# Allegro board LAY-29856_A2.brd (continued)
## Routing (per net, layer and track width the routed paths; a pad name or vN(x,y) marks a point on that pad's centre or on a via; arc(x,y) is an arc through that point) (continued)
SDA_USB_CONN_DP: length 4.6
  TOP w0.119: R190.1 123.38,82.36 123.38,82.62 U19.1 123.39,84.01 123.39,84.85 123.19,85.05 J23.3
SDA_USB_DN: length 5.5
  TOP w0.119: v1(124.84,80.06) 124.54,79.76 123.73,79.76 123.33,79.36 123.33,79.13 123.19,78.98 U16.4 ; R189.2 123.63,80.7 123.63,80.46 v1(123.83,80.26)
  BOTTOM w0.119: v1(124.84,80.06) 124.6,79.82 123.76,79.82 123.64,79.94 123.64,80.08 v1(123.83,80.26)
SDA_USB_DP: length 5.4
  TOP w0.119: U16.3 123.69,78.98 123.58,79.09 123.58,79.26 123.83,79.51 124.67,79.51 v1(124.84,79.34) ; R190.2 123.32,80.77 123.32,80.47 v1(123.11,80.26)
  BOTTOM w0.119: v1(124.84,79.34) 124.6,79.58 123.66,79.58 123.39,79.84 123.39,79.98 v1(123.11,80.26)
SDA_USB_P5V_SENSE: length 5.2
  TOP w0.127: U16.30 126.1,76.82 127.51,78.24 R200.2 R203.1
SDA_VOUT33: length 3.8
  TOP w0.127: U16.5 122.69,79.75 122.17,80.26 C162.1 122.17,81.03 R181.2
SDA_XTAL: length 6.6
  TOP w0.127: U16.18 121.69,73.04 119.89,71.25 119.63,71.25 C160.1 118.43,70.05 Y3.1
SDRAM_3V3: length 51.9
  TOP w0.381: v1(85.85,51.05) 86.49,51.69 88.27,51.69 v1(88.9,51.05) 89.53,51.69 91.82,51.69 v1(92.46,51.05) 93.09,51.69 94.82,51.69 95.45,51.05 ; U14.3 v1(102.65,58.33) ; U14.49 v1(100.25,51.44) ; v1(91.19,57.28) 90.68,57.28 89.79,58.17 82.55,58.17 82.3,58.42 C149.1 81.53,59.44 82.04,59.94 83.06,59.94 83.45,60.34 U14.27 ; 95.45,51.05 95.83,51.44 v1(98.81,51.44) ; 95.45,51.05 U14.43 ; U14.14 v1(93.85,58.67) ; U14.9 v1(97.85,58.67) ; U14.1 v1(104.25,58.29)
  BOTTOM w0.381: v1(88.9,51.05) R314.1 R315.1 ; R270.1 R269.1 v1(92.46,51.05) ; R268.1 98.81,52.45 ; R266.1 98.81,54.99 ; R265.1 98.81,56.26 ; R271.1 v1(85.85,51.05) ; C147.1 v1(98.81,51.44) ; R267.1 98.81,53.72
SEMC_A0: length 3.5
  TOP w0.127: R299.1 70.1,57.52 70.1,56.77 69.73,56.39 U1.142
SEMC_A1: length 3.3
  TOP w0.127: R300.1 70.61,57.14 70.61,56.39 70.12,55.89 U1.141
SEMC_A2: length 6.4
  TOP w0.127: U1.140 70.5,55.39 71.18,56.07 71.18,56.25 70.98,56.45 70.98,56.63 71.16,56.81 71.34,56.81 71.54,56.61 72.1,56.61 72.9,57.4 72.9,57.52 R301.1
SEMC_A3: length 5.3
  TOP w0.127: R302.1 72.52,56.13 71.75,56.13 70.51,54.89 U1.139
SEMC_A4: length 5.1
  TOP w0.127: U1.138 69.72,54.39 69.81,54.48 70.61,54.48 71.88,55.75 R303.1
SEMC_A5: length 4.9
  TOP w0.127: U1.137 69.72,53.89 69.97,54.14 70.7,54.14 71.3,54.74 R288.1
SEMC_A6: length 4.8
  TOP w0.127: U1.136 69.65,53.39 70.1,53.84 71.89,53.84 72.01,53.72 R289.1
SEMC_A7: length 2.5
  TOP w0.127: R290.1 69.8,51.89 U1.133
SEMC_A8: length 2.4
  TOP w0.127: U1.132 70.19,51.39 R295.1
SEMC_A9: length 5
  TOP w0.127: U1.131 70.23,50.89 70.65,51.31 72.52,51.31 R294.1
SEMC_A10: length 3.7
  TOP w0.127: R297.1 69.72,58.03 69.72,57.15 69.46,56.89 U1.143
SEMC_A11: length 4.8
  TOP w0.127: R296.1 70.89,50.93 70.36,50.39 U1.130
SEMC_A12: length 5.1
  TOP w0.127: U1.129 70.59,49.89 71.25,50.55 72.4,50.55 R298.1
SEMC_BA0: length 6.1
  TOP w0.127: U1.2 66.16,60.19 66.42,60.45 67.56,60.45 67.82,60.2 69.6,60.2 70.48,61.09 R291.1
SEMC_BA1: length 5.2
  TOP w0.127: U1.1 66.66,59.93 66.8,60.07 67.44,60.07 67.74,59.77 69.8,59.77 70.23,60.2 R293.1
SEMC_CAS: length 4
  TOP w0.127: U1.7 63.66,60.11 63.96,60.4 64.16,60.4 65.61,61.85 R307.1
SEMC_CKE: length 4.6
  TOP w0.127: U1.127 70.36,48.89 70.48,48.77 R306.1
SEMC_CLK: length 2.6
  TOP w0.127: U1.126 70.1,48.39 70.28,48.21 R177.1
SEMC_CS0: length 4.1
  TOP w0.127: R311.1 66.04,60.83 65.66,60.46 U1.3
SEMC_D0: length 21.4
  TOP w0.127: U1.18 58.16,60.19 65.15,67.18 69.29,67.18 72.59,70.48 74.05,70.48 R272.2
SEMC_D1: length 22.8
  TOP w0.127: R273.2 75.47,70.1 75.22,69.85 74.96,69.85 74.71,70.1 74.46,70.1 74.2,69.85 73.95,69.85 73.69,70.1 72.64,70.1 69.42,66.88 65.28,66.88 58.66,60.26 U1.17
SEMC_D2: length 23.7
  TOP w0.127: R274.2 77.73,69.47 72.52,69.47 69.62,66.57 65.41,66.57 59.16,60.33 U1.16
SEMC_D3: length 25
  TOP w0.127: R275.2 79.64,69.09 72.64,69.09 69.82,66.27 65.53,66.27 59.66,60.4 U1.15
SEMC_D4: length 26.8
  TOP w0.127: R276.2 81.54,68.45 72.9,68.45 69.76,65.32 65.44,65.32 61.93,61.8 61.93,61.19 61.67,60.93 60.81,60.93 60.16,60.29 U1.14
SEMC_D5: length 27.8
  TOP w0.127: R277.2 83.27,68.15 73.03,68.15 69.89,65.01 65.57,65.01 62.23,61.67 62.23,61.06 61.8,60.63 61.01,60.63 60.66,60.28 U1.13
SEMC_D6: length 29
  TOP w0.127: U1.12 61.16,60.17 61.32,60.33 61.93,60.33 62.53,60.93 62.53,61.54 65.7,64.71 70.02,64.71 73.15,67.84 85.25,67.84 R278.2
SEMC_D7: length 29.7
  TOP w0.127: R279.2 87.1,67.54 73.28,67.54 70.14,64.4 65.82,64.4 62.84,61.42 62.84,60.81 62.16,60.13 U1.10
SEMC_D8: length 17.6
  TOP w0.127: R283.2 83.62,43.89 77.01,43.89 74.68,46.23 72.14,46.23 70.97,47.39 U1.124
SEMC_D9: length 23
  TOP w0.127: R284.2 86.42,42.47 83.98,42.47 83.86,42.6 83.86,42.8 83.73,42.93 83.47,42.93 83.35,42.8 83.35,42.6 83.22,42.47 82.97,42.47 82.84,42.6 82.84,42.93 82.71,43.05 82.46,43.05 82.33,42.93 82.33,42.6 82.2,42.47 81.92,42.47 81.85,42.53 81.85,42.8 81.72,42.93 76.58,42.93 74.93,44.58 74.31,44.58 74.18,44.7 74.18,45.21 74.05,45.34 73.8,45.34 73.67,45.21 73.67,44.7 73.55,44.58 73.28,44.58 73.15,44.7 73.15,45.09 73.03,45.21 72.52,45.21 70.84,46.89 U1.123
SEMC_D10: length 14.5
  TOP w0.127: U1.122 70.87,46.39 73.06,44.2 74.8,44.2 76.45,42.55 76.71,42.55 76.83,42.42 76.83,42.29 76.96,42.16 77.21,42.16 77.34,42.29 77.34,42.42 77.47,42.55 79.33,42.55 79.46,42.42 79.46,42.29 79.58,42.16 79.84,42.16 79.96,42.29 79.96,42.42 80.09,42.55 80.27,42.55 R285.2
SEMC_D11: length 19.5
  TOP w0.127: R286.2 82.3,41.27 80.3,41.27 80.17,41.4 80.17,41.66 80.04,41.78 79.79,41.78 79.66,41.66 79.66,41.4 79.53,41.27 79.28,41.27 79.15,41.4 79.15,42.04 79.03,42.16 78.77,42.16 78.65,42.04 78.65,41.4 78.52,41.27 78.26,41.27 78.14,41.4 78.14,42.04 78.01,42.16 77.76,42.16 77.63,42.04 77.63,41.4 77.5,41.27 77.22,41.27 74.65,43.84 72.97,43.84 70.92,45.89 U1.121
SEMC_D12: length 18.3
  TOP w0.127: U1.120 70.03,45.39 72.19,43.23 73.81,43.23 76.5,40.54 84.23,40.54 R287.2
SEMC_D13: length 19.9
  TOP w0.127: U1.119 70.09,44.89 72.06,42.93 73.67,42.93 76.36,40.23 85.96,40.23 R280.2
SEMC_D14: length 21.8
  TOP w0.127: R281.2 87.94,39.93 76.21,39.93 73.52,42.62 71.93,42.62 69.98,44.58 69.72,44.58 69.54,44.39 U1.118
SEMC_D15: length 23.4
  TOP w0.127: U1.117 70.23,43.89 71.83,42.29 73.41,42.29 76.07,39.62 89.92,39.62 R282.2
SEMC_DM0: length 31.9
  TOP w0.127: R310.1 89.41,67.76 89.28,67.89 88.9,67.89 88.77,67.77 88.77,67.44 88.57,67.23 73.41,67.23 70.27,64.1 65.95,64.1 63.14,61.29 63.14,60.68 62.66,60.2 U1.9
SEMC_DM1: length 24.4
  TOP w0.127: U1.125 69.97,47.89 70.16,47.7 71.3,47.7 72.39,46.61 74.8,46.61 75.1,46.31 75.28,46.31 75.42,46.45 75.6,46.45 75.78,46.27 75.78,46.09 75.64,45.95 75.64,45.77 75.82,45.59 76,45.59 76.14,45.73 76.32,45.73 76.5,45.55 76.5,45.37 76.36,45.23 76.36,45.05 76.54,44.87 76.72,44.87 76.86,45.01 77.04,45.01 77.22,44.83 77.22,44.65 77.08,44.51 77.08,44.33 77.22,44.2 77.51,44.2 77.63,44.32 77.63,44.58 77.76,44.7 78.02,44.7 78.14,44.58 78.14,44.32 78.27,44.2 78.52,44.2 78.65,44.32 78.65,44.58 78.78,44.7 79.03,44.7 79.16,44.58 79.16,44.32 79.29,44.2 79.54,44.2 79.67,44.32 79.67,44.58 79.79,44.7 80.05,44.7 80.17,44.58 80.17,44.32 80.3,44.2 80.56,44.2 80.68,44.32 80.68,44.58 80.81,44.7 81.06,44.7 81.19,44.58 81.19,44.32 81.32,44.2 81.57,44.2 81.7,44.32 81.7,44.58 81.83,44.7 82.08,44.7 82.21,44.58 82.21,44.32 82.33,44.2 82.59,44.2 82.71,44.32 82.71,44.58 82.84,44.7 83.1,44.7 83.22,44.58 83.22,44.32 83.35,44.2 83.69,44.2 83.82,44.32 83.82,44.58 83.95,44.7 84.33,44.7 84.46,44.57 R309.1
SEMC_DQS: length 2.4
  TOP w0.127: 70.99,49.4 70.98,49.39 U1.128
SEMC_RAS: length 6.5
  TOP w0.127: U1.4 65.16,60.46 65.91,61.21 67.82,61.21 67.94,61.34 67.94,62.36 68.07,62.48 68.33,62.48 68.46,62.35 R308.1
SEMC_WE: length 5.8
  TOP w0.127: R304.1 65.68,62.37 65.5,62.37 65.42,62.45 65.24,62.45 65.06,62.27 65.06,62.09 65.14,62.01 65.14,61.83 64.96,61.65 64.78,61.65 64.7,61.73 64.52,61.73 64.34,61.55 64.34,61.37 64.42,61.29 64.42,61.11 64.04,60.73 63.78,60.73 63.16,60.11 U1.8
SENSOR_3V3: length 42.4
  TOP w0.305: U26.14 61.59,86.99 C167.1 ; 57.67,83.93 U26.1
  TOP w0.381: R241.1 v1(65.79,84.45) 63.12,87.12 v1(62.61,87.12) C167.1 ; R239.2 56,84.72 C168.1 v1(57.02,84.58) 57.67,83.93 ; R240.1 v1(65.53,79.38) ; R245.1 v1(67.94,81.41) ; R249.1 v1(57.02,81.15) 57.02,79.76 v1(58.04,78.74) R250.1 ; R247.1 v1(61.09,77.22)
  BOTTOM w0.381: v1(62.61,87.12) 59.56,87.12 v1(57.02,84.58) 57.78,83.82 57.78,81.92 v1(57.02,81.15) ; v1(65.53,79.38) 65.91,79.38 v1(67.94,81.41) 66.67,82.68 66.67,83.57 v1(65.79,84.45) ; v1(58.04,78.74) 59.56,78.74 v1(61.09,77.22)
SPK_LN: length 6.2
  TOP w0.107: R105.1 51.93,21.21 52.22,21.21 52.83,21.83 52.83,24.78 53.6,25.55 U10.23
SPK_LP: length 6.2
  TOP w0.107: R107.1 51.94,20.95 52.32,20.95 53.09,21.72 53.09,23.95 53.2,24.05 54.05,24.05 54.1,24 54.53,24 54.76,24.24 U10.25
SPK_RN: length 3.3
  TOP w0.107: R104.1 51.56,27.77 51.66,27.67 52.09,27.67 52.5,27.25 53.29,27.25 53.58,27.55 U10.19
SPK_RP: length 3.3
  TOP w0.107: U10.22 53.39,26.05 52.84,26.6 52.84,26.76 52.61,27 52.39,27 51.98,27.41 51.78,27.41 R106.1
SW1_RST_B: length 41.5
  TOP w0.127: SW5.3 SW5.4 102.46,82.46 C158.1 105.84,79.08 105.84,75.64 110.62,70.87 110.62,60.07 J22.2
SWD_CLK_TGTMCU_BUF: length 3.1
  TOP w0.127: U24.4 134.49,51.66 134.46,51.69 J28.1
SWD_DIO_TGTMCU_BUF: length 9.1
  TOP w0.127: v1(135,60.58) 135.21,60.37 U22.6 ; J27.1 134.46,56.39 134.49,56.36 U23.4
  BOTTOM w0.127: J27.1 132.72,58.29 v1(135,60.58)
TC_EXTAL_TP: length 5.1
  TOP w0.127: TP20.1 118.11,79.25 120.03,77.32 U16.10
TC_SDA_USB_ID_TP: length 4.5
  TOP w0.127: TP19.1 120.65,84.2 122.05,84.2 122.54,84.69 J23.4
TC_XTAL_TP: length 3.8
  TOP w0.127: U16.9 120.3,77.82 119.76,78.36 TP21.1
TP_2102_A: length 1.9
  TOP w0.127: U15.3 119.25,60.71 TP17.1
TP_2102_B: length 2.5
  TOP w0.127: TP18.1 120.52,65.41 119.65,64.54 U15.6
UART1_RX_TGTMCU_BUF: length 3.1
  TOP w0.127: J25.1 132.75,65.76 U21.4
UART1_RX_TGTMCU_R: length 16.5
  TOP w0.127: U21.3 136.49,66.58 135.25,67.82 129.92,67.82 125.76,71.98 125.76,74.14 125.58,74.32 U16.25
UART1_TX_TGTMCU_BUF: length 3.5
  TOP w0.127: J26.1 133.78,60.02 U22.7
UART1_TX_TGTMCU_R: length 24.2
  TOP w0.127: v1(126.75,72.39) 130.56,68.58 135.64,68.58 138.18,66.04 138.18,61.21 136.98,60.02 U22.2 ; v1(124.97,72.52) 124.69,72.8 U16.24
  BOTTOM w0.127: v1(126.75,72.39) 125.09,72.39 v1(124.97,72.52)
USER_BUTTON: length 52
  TOP w0.127: U1.52 46.37,49.89 45.59,50.67 TP6.1 44.07,50.29 38.73,50.29 38.07,50.95 35.92,50.95 34.98,51.89 23.8,51.89 21.08,54.61 20.19,54.61 v1(20.07,54.74) ; SW4.4 SW4.3 9.25,56.03 C174.1 12.17,56.01 v1(12.19,56.03)
  BOTTOM w0.127: v1(12.19,56.03) 18.64,56.03 19.94,54.74 v1(20.07,54.74)
VAUD_3V3: length 54.8
  TOP w0.305: U10.32 58.27,24.28 v1(58.93,23.62) 59.56,23.62 60.07,23.11 C93.1 ; U10.10 57.77,29.95 v1(58.55,30.73) ; v1(59.94,28.83) 59.66,28.55 U10.8
  TOP w0.381: C91.1 60.45,30.23 C94.1 C92.1 60.45,28.83 v1(59.94,28.83) ; C91.1 59.56,31.11 59.18,30.73 v1(58.55,30.73) ; C91.1 60.45,32 R80.2 ; v1(52.7,29.21) 52.7,29.97 51.69,30.99 51.18,30.99 50.8,31.37 50.8,32.51 51.18,32.89 R93.1 51.56,33.53 v1(51.82,33.78) ; v1(53.34,33.78) R92.1 ; C93.1 61.47,22.35 65.41,18.41 65.41,17.14 66.23,16.32 v1(66.23,14.41) ; v1(60.07,8.26) 59.82,8 R81.1
  BOTTOM w0.381: v1(59.94,28.83) 58.93,27.81 v1(58.93,23.62) ; v1(58.55,30.73) 57.02,29.21 v1(52.7,29.21) ; v1(66.23,14.41) v1(60.07,8.26) ; v1(51.82,33.78) v1(53.34,33.78)
VLDO_3V3: length 72.2
  TOP w0.381: v1(48.64,65.66) R44.1 ; C43.1 24.96,49.46 U3.5 ; C43.1 26.27,49.4 26.54,49.67 v1(26.54,51.04) ; C43.1 25.02,48.39 C42.1 25.01,48.37 R32.1 28.19,45.97 v1(28.57,45.59) R36.1 ; R49.1 37.97,37.21 33.91,41.27 v1(29.84,41.27) ; v1(46.74,64.9) 45.72,65.91 42.29,65.91 39.12,69.09 34.87,69.09 34.49,68.71 34.49,66.85 35.36,65.99 v1(35.36,58.17)
  BOTTOM w0.381: v1(28.57,45.59) 29.84,44.32 v1(29.84,41.27) ; v1(46.74,64.9) 47.5,65.66 v1(48.64,65.66) ; v1(35.36,58.17) 28.45,58.17 26.54,56.26 v1(26.54,51.04)
VSD_3V3: length 44.2
  TOP w0.254: 23.93,57.84 U27.A2
  TOP w0.381: J15.4 v1(22.57,80.17) ; v1(22.48,74.8) 22.36,74.68 R358.1 16.89,68.83 14.61,66.55 v1(14.61,57.78) ; 23.93,57.84 24,57.91 C30.1 24.77,57.03 23.88,56.13 21.08,56.13 20.32,56.9 v1(20.07,56.9)
  BOTTOM w0.381: v1(20.07,56.9) 19.18,57.78 v1(14.61,57.78) ; v1(22.48,74.8) C139.1 22.61,78.24 C138.1 22.61,80.13 v1(22.57,80.17)
VTRG_FAULT_B: length 14.4
  TOP w0.127: U25.A2 134.24,76.08 R209.2 132.45,76.97 131.95,77.47 131.95,79.25 131.19,80.01 127.89,80.01 125.7,77.82 U16.32
WALL_OV_BASE: length 1.4
  TOP w0.127: Q3.1 19.34,10.84 R5.2
WALL_OV_CTL: length 2.5
  TOP w0.127: R3.2 18.55,9.4 R5.1 18.55,11.74 D1.C
WALL_OVP_LED: length 12.8
  TOP w0.127: R10.1 19.42,13.72 20.11,13.04 Q3.3 23.75,13.04 D2.A
N99781517: length 7.9
  TOP w0.381: D6.C 31.74,49.82 R17.2 32.22,48.55 D4.C J6.1 34.92,48.26 R16.1
N99781633: length 11
  TOP w0.305: U1.65 46.06,43.39 46.03,43.37 44.38,43.37 42.54,41.52 C21.1
  TOP w0.381: C22.1 C21.1
N99781636: length 2.7
  TOP w0.305: U1.56 45.48,47.89 45.35,47.76 C24.1
N99781637: length 5.2
  TOP w0.305: C25.1 C26.1 46.35,39.5 46.75,39.89 U1.72
N99781682: length 6.2
  TOP w0.127: Y2.1 41.8,48.11 42.54,47.38 C44.1 43.68,47.38 43.79,47.27 45.62,47.27 45.73,47.38 47.2,47.38 U1.57
N99781687: length 6.3
  TOP w0.127: Y2.2 41.8,45.61 42.79,46.6 C45.1 43.85,46.89 U1.58
N99781695: length 7.9
  TOP w0.127: Y4.1 41.3,39.24 C37.1 43.93,39.24 R30.2 44.33,39.25 44.58,39.5 44.58,40.26 46.21,41.89 U1.68
N99781702: length 9.4
  TOP w0.127: U1.67 45.95,42.39 45.43,41.87 45.43,41.57 44.75,40.89 R31.1 R30.1 43.93,40.01 C36.1 42.68,40.01 42.29,39.62 40.56,39.62 40.01,40.17 Y4.3
N99781716: length 5.5
  TOP w0.381: R21.1 27.47,55.71 U2.3 C29.1 26.68,57.41 R20.2
N99781728: length 2.4
  TOP w0.381: U2.2 28.74,53.51 R21.2 R22.1
N99781740: length 2.6
  TOP w0.127: C61.2 R53.1 23.37,39.62 D10.C
N99781746: length 4.6
  TOP w0.127: U5.3 19.85,37.17 R46.1 21.89,36.44 D9.A D10.A
N99781747: length 4
  TOP w0.508: J8.2 30.18,35.1 ; J8.2 30.18,36.53 ; J8.2 28.75,36.53 ; J8.2 28.75,35.1
N99781749: length 7.8
  TOP w0.127: U4.8 21.76,32.43 21.46,32.12 R39.2 C54.1 19.16,33.03 R41.1 19.04,33.15 19.04,34.9 U5.2 19.85,34.97 R46.2
N99781753: length 2.6
  TOP w0.127: R50.2 C59.1 21.96,38.07 D9.C
N99781762: length 3.2
  TOP w0.305: R39.1 22.09,31.38 22.41,31.06 U4.2
N99781782: length 3
  TOP w0.127: U4.7 22.41,34.99 R42.1 R40.2
N99781791: length 3.4
  TOP w0.457: U4.3 23.06,29.39 23.37,29.08 25.53,29.08
N99808656: length 7.4
  TOP w0.305: U1.44 44.2,53.89 43.61,54.48
  TOP w0.381: R60.2 C76.1 41.66,54.62 41.79,54.48 C77.1 43.61,54.48
N99815013: length 8.9
  TOP w0.127: L9.2 C126.1 90.04,11.81 C127.1 89.41,12.06 89.41,14.86 89.79,15.24 89.79,16.51 88.89,17.41 U11.3
N99815680: length 7.3
  TOP w0.127: U11.2 88.88,16.91 89.41,16.38 89.41,15.49 88.9,14.99 88.9,12.45 C129.1 C128.1
N99815919: length 4
  TOP w0.127: C135.1 110.49,12.58 J14.6
N99815924: length 4
  TOP w0.127: C136.1 110.5,13.6 J14.5
N99820323: length 5.1
  TOP w0.127: R117.1 90.04,23.24 88.9,22.1 87.63,22.1 87.1,21.57 U11.10
N99825452: length 10.3
  TOP w0.305: U10.21 53.59,26.55 v1(53.34,26.8) ; U10.26 55.26,23.64
  TOP w0.381: 55.26,23.64 v1(54.99,23.37) C96.1 C95.1 54.99,19.82 R82.2
  BOTTOM w0.381: v1(53.34,26.8) C99.1 53.47,25.78 C97.1 v1(54.99,23.37)
N99827287: length 2.1
  TOP w0.127: C100.1 55.76,22.84 U10.27
N99827729: length 2.9
  TOP w0.127: R83.2 55.26,31.78 U10.15
N99827749: length 3.5
  TOP w0.127: U10.13 56.26,30.74 56.48,30.96 56.74,30.96 56.97,31.19 56.97,31.45 R85.2
N99827769: length 3.6
  TOP w0.127: U10.12 56.77,30.23 R87.2
N99827789: length 2.9
  TOP w0.127: R88.2 54.48,30.99 54.76,30.71 U10.16
N99827809: length 3.1
  TOP w0.127: U10.14 55.76,31.26 R89.2
N99827829: length 4.1
  TOP w0.127: R90.2 58.92,31.37 58.42,31.37 57.27,30.21 U10.11
N99827958: length 5.5
  TOP w0.107: J12.2 46.74,27.92 46.84,27.82 48.89,27.82 C120.2 49.28,27.94 49.92,27.94 C122.1 50.16,27.94 50.55,27.94 R104.2
N99827962: length 5.5
  TOP w0.107: J12.1 46.74,27.45 46.84,27.56 48.89,27.56 C124.1 49.28,27.43 49.92,27.43 C122.2 50.16,27.43 50.55,27.43 R106.2
N99828318: length 5.5
  TOP w0.107: J13.2 46.74,21.32 46.84,21.21 48.89,21.21 C121.2 49.28,21.34 49.92,21.34 C123.1 50.16,21.34 50.55,21.34 R105.2
N99828322: length 5.5
  TOP w0.107: J13.1 46.74,20.85 46.84,20.95 48.89,20.95 C125.1 49.28,20.83 49.92,20.83 C123.2 50.16,20.83 50.55,20.83 R107.2
N99833017: length 6.4
  TOP w0.305: J9.1 4.6,44.99 5.9,46.29 L3.1 7.05,45.85 8,45.85 8.63,45.21 U8.6
N99833020: length 4.5
  TOP w0.305: R68.1 7.11,42.3 U8.3 6.49,43.31 6.21,43.04 J9.4
N99833038: length 9
  TOP w0.119: v1(9.65,44.3) 9.89,44.06 10.02,44.06 10.31,44.34 L4.2 11.07,44.34 R61.1 ; U8.1 6.65,44.32 6.52,44.19 6.2,44.19 v1(5.97,44.42) 5.73,44.18 5.1,44.18 4.94,44.34 J9.2
  BOTTOM w0.119: v1(5.97,44.42) 6.19,44.2 7.71,44.2 7.85,44.07 9.42,44.07 v1(9.65,44.3)
N99833040: length 9
  TOP w0.119: U8.2 6.67,43.81 6.59,43.89 6.17,43.89 v1(5.97,43.69) 5.73,43.93 5.18,43.93 4.94,43.69 J9.3 ; v1(9.65,43.59) 9.88,43.81 10.05,43.81 10.31,43.54 L4.3 11.07,43.54 R63.1
  BOTTOM w0.119: v1(5.97,43.69) 6.23,43.95 7.61,43.95 7.74,43.82 9.42,43.82 v1(9.65,43.59)
N99838171: length 1.5
  TOP w0.127: D12.C 112.14,46.23 R145.1
N99881896: length 1.5
  TOP w0.127: R183.1 U15.5
N99882483: length 11.9
  TOP w0.127: R180.2 118.1,61.46 v1(118.11,61.47) 118.85,62.21 U15.2 ; J22.1 115.06,56.64 v1(115.82,56.64) 115.82,57.4 R188.2
  BOTTOM w0.127: v1(118.11,61.47) 115.82,59.18 v1(115.82,56.64)
N99903207: length 2.3
  TOP w0.381: L6.1 R86.2 58.55,20.83 C102.2
N99903209: length 2.3
  TOP w0.381: L7.1 R91.1 57.65,20.71 C103.2
N99903219: length 11.9
  TOP w0.381: v1(57.66,12.83) 57.7,12.79 TVS4.2 57.65,11.64 J11.3 ; L7.2 C104.1 v1(56.13,18.17)
  BOTTOM w0.381: v1(57.66,12.83) 57.7,12.87 57.7,16.6 v1(56.13,18.17)
N99903223: length 24
  TOP w0.381: v1(60.08,18.17) C101.2 L6.2 ; J11.2 44.59,11.64 TVS2.2 v1(44.54,12.57)
  BOTTOM w0.381: v1(44.54,12.57) 48.9,12.57 55.12,18.8 59.45,18.8 v1(60.08,18.17)
N99903738: length 37.6
  TOP w0.381: v1(67.69,13.08) 67.69,16.26 66.42,17.53 66.42,19.43 v1(65.02,20.83) ; v1(64.14,21.84) 63.75,22.23 L8.2 ; J11.4 48.75,3.66 49.78,4.7 57.57,4.7 TVS5.2 58.71,3.56 60.2,3.56 v1(61.21,4.57)
  BOTTOM w0.381: v1(61.21,4.57) 67.69,11.05 v1(67.69,13.08) ; v1(64.14,21.84) 64.14,21.72 v1(65.02,20.83)
N99904959: length 2.1
  TOP w0.381: R97.2 R100.1 64.9,25.27 C112.2
N99904961: length 4.2
  TOP w0.381: L8.1 C117.1 C118.1 R100.2 64.94,24.52 C115.2
N99904975: length 3.3
  TOP w0.381: R97.1 65.14,27.69 C109.1 63.76,27.69 C108.1 R94.2
N99907436: length 1.8
  TOP w0.127: R103.2 R102.2 C113.2
N99907447: length 3.6
  TOP w0.127: R101.2 68.97,22.23 R99.2 ; R102.1 67.82,22.99 R99.2 ; R99.2 68.97,24.25 C114.1
N99907449: length 3.5
  TOP w0.127: R99.1 70.75,22.99 R96.2 ; R99.1 69.72,24.38 C111.1 ; R99.1 69.72,22.23 R98.2
N99907458: length 9.8
  TOP w0.127: C113.1 v1(66.8,22.23) ; R96.1 C106.1 71,24.52 C105.1 v1(71.88,23.88) R95.2
  BOTTOM w0.127: v1(66.8,22.23) 67.31,22.73 70.74,22.73 v1(71.88,23.88)
N99907542: length 3.3
  TOP w0.127: P1.1 69.85,18.54 R98.1
N99907546: length 3.4
  TOP w0.127: P1.2 68.83,18.66 R101.1
N99909350: length 4.1
  TOP w0.127: R248.1 R247.2 U26.7
N99909356: length 3.1
  TOP w0.127: R244.1 60.59,87.25 U26.16
N99909379: length 3.3
  TOP w0.127: U26.6 60.59,79.12 R252.1
N99909383: length 3.9
  TOP w0.127: U26.4 56.14,82.43 R251.1
N99909400: length 3.7
  TOP w0.127: U26.2 56.14,83.43 C170.1
N99909418: length 3.8
  TOP w0.127: C169.1 63.12,78.87 61.59,80.4 U26.8
N99909466: length 4.7
  TOP w0.127: U26.9 64.89,81.93 R243.1
N99909468: length 4.3
  TOP w0.127: U26.11 65.92,82.93 R242.1
N99909488: length 5.1
  TOP w0.127: U26.10 66.42,82.43 R246.1 R245.2
N99916564: length 23.6
  TOP w0.127: J18.5 80.16,74.68 77.47,74.68 75.79,76.35 63.75,76.35 63.22,75.82 60.06,75.82 R163.1
N99916634: length 21.7
  TOP w0.127: R165.1 58.17,75.56 58.72,76.12 63.04,76.12 63.58,76.66 78.78,76.66 J18.6
N99916953: length 8.8
  TOP w0.127: 113.28,68.96 113.28,72.63 J20.3
N99916957: length 4.4
  TOP w0.381: J20.5 104.59,77.63 D14.C
N99917118: length 3.2
  TOP w0.127: J19.9 R173.1
N100002783: length 4
  TOP w0.305: R33.2 45.72,59.18 46.35,58.55 46.35,57.7 46.66,57.39 U1.37
  TOP w0.381: C46.1 R33.2
N100054133: length 2.4
  TOP w0.127: Q4.1 10.62,14.78 R11.1 R10.2
N100054172: length 7.6
  TOP w0.508: 27.3,2.16 JP1.2 ; JP1.2 28.19,3.05 ; JP1.2 27.3,3.94 ; JP1.2 26.42,3.05 ; J1.1 33.02,12.32 ; J1.1 34.04,11.3 ; J1.1 32,11.3 ; J1.1 33.02,10.29
N100054253: length 5.4
  TOP w0.305: R8.1 24.47,11.05 D2.C 24.26,9.65 C5.2 24.25,9.39 R4.2 24.99,7.77 Q2.3
N100054255: length 1
  TOP w0.381: R8.2 R9.1
N100054257: length 7.9
  TOP w0.381: R9.2 25.53,12.95 24.13,14.35 23.25,14.35 SW1.5
N100054299: length 4.8
  TOP w0.305: Q3.2 22.54,9.59
  TOP w0.508: JP1.1 24.77,3.94 ; JP1.1 25.65,3.05 ; JP1.1 23.88,3.05 ; JP1.1 24.77,2.16
N100054525: length 1.6
  TOP w0.127: R7.2 8.81,22.79 D3.3
N100054552: length 2.1
  TOP w0.127: D3.1 8.81,17.69 R6.2
N100054568: length 1.8
  TOP w0.127: Q4.3 11.56,19.55 D3.2
N100226419: length 1.8
  BOTTOM w0.127: SW8.6 96.9,54.99
N100226426: length 1.8
  BOTTOM w0.127: SW8.7 96.9,53.72
N100226433: length 1.8
  BOTTOM w0.127: SW8.8 96.9,52.45
N100585007: length 29.2
  TOP w0.127: J15.7 25.87,79.8 26.07,79.59 26.07,79.16 25.62,78.7 25.62,78.52 25.8,78.34 25.98,78.34 26.43,78.8 26.61,78.8 26.79,78.62 26.79,78.44 26.29,77.94 26.29,77.75 26.46,77.57 26.64,77.57 27.15,78.08 27.33,78.08 27.51,77.9 27.51,77.72 27.05,77.27 27.05,77.09 27.23,76.91 27.41,76.91 27.87,77.36 28.05,77.36 28.23,77.18 28.23,77 27.85,76.62 27.85,76.44 28.03,76.26 28.21,76.26 28.59,76.64 28.77,76.64 28.95,76.46 28.95,76.28 28.87,76.21 28.87,76.03 29.31,75.6 31.21,75.6 33.08,73.73 33.08,71.18 32.51,70.61 32.51,65.15 33.4,64.26 R363.2
N100585009: length 24.7
  TOP w0.127: R364.2 33.15,70.61 33.4,70.87 33.4,74.09 30.91,76.58 30.59,76.58 30,75.99 29.82,75.99 29.66,76.16 29.66,76.36 30.3,77.01 30.3,77.19 30.12,77.37 29.94,77.37 29.46,76.89 29.28,76.89 29.1,77.07 29.1,77.25 29.58,77.73 29.58,77.91 29.4,78.09 29.22,78.09 28.74,77.61 28.56,77.61 28.38,77.79 28.38,77.97 28.86,78.45 28.86,78.63 28.68,78.8 28.5,78.8 28.02,78.33 27.84,78.33 27.67,78.51 27.67,78.69 28.14,79.16 28.14,79.34 27.96,79.52 27.78,79.52 27.31,79.05 27.13,79.05 26.95,79.23 26.95,79.41 27.43,79.89 27.43,80.07 27.23,80.26 27.05,80.26 26.97,80.35 J15.8
N100585016: length 23.1
  TOP w0.127: J15.1 19.27,80.05 26.42,72.9 27.81,72.9 28.57,72.14 R360.2
N100585038: length 25
  TOP w0.127: R362.2 30.61,71.12 31.01,71.53 31.01,73.13 30.23,73.91 28.61,73.91 28.36,73.67 27.73,73.67 27.48,73.92 27.22,73.92 27.09,73.79 26.59,73.79 21.47,78.91 J15.3
N100585089: length 21.7
  TOP w0.127: J15.2 20.37,79.45 26.54,73.28 28.19,73.28 29.2,72.27 R140.1 30.1,71.75 29.59,71.25 R361.2
N100640762: length 3.2
  TOP w0.127: J19.10 R174.1
N100756566: length 4.2
  TOP w0.127: U1.71 46.36,40.39 45.72,39.75 45.72,37.85 TP7.1
N100757315: length 2.5
  TOP w0.127: TP13.1 45.18,42.89 U1.66
N100763759: length 41.1
  TOP w0.127: R138.2 39.71,53.26 38.94,53.26 C141.1 37.84,53.47 36.98,54.33 34.75,54.33 32.11,56.97 32.11,59.97 31.5,60.58 31.5,70.87 32,71.37 32,73.53 30.86,74.68 27.3,74.68 25.92,76.06 25.67,76.06 25.49,76.24 25.49,76.42 25.62,76.56 25.62,76.74 25.44,76.92 25.26,76.92 25.13,76.78 24.95,76.78 24.82,76.91 24.82,77.09 24.95,77.23 24.95,77.41 24.77,77.59 24.59,77.59 24.46,77.45 24.28,77.45 23.67,78.06 J15.5
N100784802: length 27.1
  TOP w0.127: J18.1 88.79,73.15 76.96,73.15 75.18,74.93 R157.1
N100784828: length 26.5
  TOP w0.127: R158.1 65.02,74.93 65.53,75.44 75.18,75.44 77.09,73.53 86.63,73.53 J18.2
N100784935: length 25.6
  TOP w0.127: R159.1 64.05,75.74 75.39,75.74 77.22,73.91 84.48,73.91 J18.3
N100784954: length 24.7
  TOP w0.127: R161.1 61.77,75.49 63.33,75.49 63.88,76.05 75.59,76.05 77.34,74.3 82.32,74.3 J18.4
N100872888: length 1.8
  TOP w0.127: R25.2 R20.1 R19.2
N100979684: length 2.5
  TOP w0.127: R32.2 R34.1 23.27,46.06 U3.4
N101050998: length 6.4
  TOP w0.127: R116.2 R118.1 86.35,11.68 C137.1 86.49,12.57 87.6,13.69 U11.32
N101100421: length 1.9
  TOP w0.381: R359.2 R139.1 R358.2
N101108824: length 1.5
  TOP w0.127: D5.A 72.25,38.24 R15.2
N101139052: length 0.8
  TOP w0.254: U7.B2 U7.B1 U7.C1
N101140611: length 5.4
  TOP w0.127: U7.A1 12.09,50.57 R66.2 R70.1 R69.2 13.97,50.68 Q9.3
N101140956: length 4.2
  TOP w0.127: R65.2 R64.2 11.44,49.27 10.54,50.16 U7.A2
N101141371: length 2.1
  TOP w0.127: R67.1 10.41,49.35 U7.A3
N101160132: length 2.8
  TOP w0.127: U25.A3 134.64,76.56 R211.1
N101160928: length 4.8
  TOP w0.127: U25.A1 133.84,75.2 132.84,76.2 R213.1 131.32,76.2 R212.2 R214.2
N101219622: length 33.8
  TOP w0.127: R177.2 72.31,48.21 73.03,47.5 76.2,47.5 78.11,45.59 78.38,45.59 78.51,45.72 78.51,45.97 78.63,46.1 78.89,46.1 79.02,45.97 79.02,45.72 79.14,45.59 79.4,45.59 79.52,45.72 79.52,45.97 79.65,46.1 79.9,46.1 80.03,45.97 80.03,45.72 80.16,45.59 80.41,45.59 80.54,45.72 80.54,45.97 80.67,46.1 80.92,46.1 81.05,45.97 81.05,45.72 81.17,45.59 81.43,45.59 81.56,45.72 81.56,45.97 81.68,46.1 81.94,46.1 82.06,45.97 82.06,45.72 82.19,45.59 82.44,45.59 82.57,45.72 82.57,45.97 82.7,46.1 82.95,46.1 83.08,45.97 83.08,45.72 83.21,45.59 83.46,45.59 83.59,45.72 83.59,45.97 83.71,46.1 83.97,46.1 84.1,45.97 84.1,45.72 84.22,45.59 84.48,45.59 84.6,45.72 84.6,45.97 84.73,46.1 84.98,46.1 85.11,45.97 85.11,45.72 85.24,45.59 85.49,45.59 85.62,45.72 85.62,45.97 85.75,46.1 86,46.1 86.13,45.97 86.13,45.72 86.25,45.59 86.51,45.59 86.64,45.72 86.64,45.97 86.76,46.1 87.02,46.1 87.14,45.97 87.14,45.8 87.27,45.67 87.52,45.67 87.65,45.8 87.65,45.97 87.78,46.1 88.03,46.1 88.16,45.97 88.16,45.72 88.29,45.59 88.54,45.59 88.67,45.72 88.67,45.97 88.79,46.1 89.05,46.1 89.18,45.97 89.18,45.72 89.3,45.59 90.55,45.59 90.68,45.47 91.82,45.47 92.1,45.75 92.1,46.84 91.82,47.12 91.44,47.12 91.06,47.5 91.06,47.88 91.19,48.01 91.31,48.01 91.44,48.13 91.44,49.44 U14.38
N101253829: length 4.1
  TOP w0.127: 41.91,70.99 42.04,71.13 C86.1 R71.2 42.93,70.23 U9.3
N101254531: length 11.1
  TOP w0.127: R77.2 C89.1 v1(51.56,80.14) ; R78.1 v1(44.07,81.03)
  BOTTOM w0.127: v1(51.56,80.14) 50.67,81.03 v1(44.07,81.03)
N101254622: length 10
  TOP w0.107: U9.7 49.91,71.5 49.41,71 48.38,71 47.63,71.75 47.63,73.28 48.01,73.66 48.39,73.66 49,74.27 FL1.4 48.12,74.56 47.88,74.8 47.88,76.08 R76.1
N101254624: length 10
  TOP w0.107: R79.1 47.62,76.08 47.62,74.8 47.38,74.56 FL1.3 46.5,74.27 47.37,73.41 47.37,71.64 48.28,70.74 49.41,70.74 49.91,70.23 U9.6
N101255204: length 5
  TOP w0.127: R74.2 R73.2 52.58,71.75 R75.1 51.57,72.77 U9.8
N101312524: length 1.1
  TOP w0.127: Q8.3 25.78,65.53 R52.2
N101312526: length 6.2
  TOP w0.127: Q8.1 26.43,63.1 26.04,63.5 25.4,63.5 24.76,64.14 R51.2 R54.1 23.95,63.19 U6.4
N101449115: length 3.3
  TOP w0.127: D8.A D7.A R28.2 R29.1
N101449483: length 1.7
  TOP w0.127: R29.2 21.72,57.92 22.04,58.24 U27.B1
N101471655: length 29
  TOP w0.127: R167.1 75.3,35.05 76.95,35.05 80.76,31.24 97.78,31.24 J19.1
N101471657: length 25
  TOP w0.127: v1(97.54,22.48) 99.7,24.64 100.23,24.64 J19.2
  BOTTOM w0.127: R168.1 85.34,14.35 91.06,14.35 97.03,20.32 97.03,21.97 v1(97.54,22.48)
N101471659: length 34.1
  TOP w0.127: v1(100.71,22.73) 108.48,22.73 J19.6
  BOTTOM w0.127: R172.1 85.59,21.46 88.39,21.46 92.33,25.4 99.19,25.4 100.71,23.88 v1(100.71,22.73)
N101471661: length 27.4
  TOP w0.127: J19.3 102.13,24 v1(99.82,24)
  BOTTOM w0.127: v1(99.82,24) 98.81,25.02 92.47,25.02 88.53,21.08 83.31,21.08 R169.1
N101471663: length 32.1
  TOP w0.127: J19.5 106.45,23.24 100.33,23.24 99.57,22.48 v1(99.06,22.48)
  BOTTOM w0.127: R171.1 84.59,19.94 89.28,19.94 93.09,23.75 97.79,23.75 v1(99.06,22.48)
N101471665: length 31.1
  TOP w0.127: J19.4 104.29,23.62 100.2,23.62 99.82,23.24 v1(99.06,23.24)
  BOTTOM w0.127: v1(99.06,23.24) 99.06,24 98.42,24.64 92.71,24.64 88.77,20.7 83.94,20.7 R170.1
N101505077: length 13.1
  TOP w0.127: J17.5 87.49,29.84 83.06,29.84 v1(82.55,30.35) ; R160.1 82.42,32.89 v1(82.42,32.64)
  BOTTOM w0.127: v1(82.42,32.64) 82.42,30.48 v1(82.55,30.35)
N101505079: length 3
  TOP w0.127: v1(83.44,26.04) 83.21,25.81 R155.1
  BOTTOM w0.127: v1(83.44,26.04) 84.27,26.87 J17.3
N101505081: length 14.8
  TOP w0.127: R162.1 82.04,32.13 v1(83.44,32.13) ; J17.6 89.53,30.35 v1(83.44,30.35)
  BOTTOM w0.127: v1(83.44,30.35) v1(83.44,32.13)
N101505083: length 3.1
  TOP w0.127: R166.1 98.55,26.41 J17.8
N101505085: length 4.1
  TOP w0.127: R164.1 96.9,25.52 J17.7
N101505087: length 20.7
  TOP w0.127: R156.1 69.84,34.42 76.57,34.42 81.65,29.34 85.46,29.34 J17.4
N101505089: length 15.7
  TOP w0.127: R154.1 69.34,34.04 76.44,34.04 81.73,28.75 J17.2
N101505091: length 15.8
  TOP w0.127: J17.1 79.19,30.77 76.23,33.73 67.86,33.73 R153.1
N101507443: length 33.1
  TOP w0.127: U14.2 103.45,62.28 95,70.74 R272.1
N101507450: length 31.7
  TOP w0.127: U14.4 101.85,62.35 101.98,62.48 102.23,62.48 102.36,62.61 102.36,62.86 102.23,62.99 101.98,62.99 101.85,63.12 101.85,63.37 101.44,63.79 101.26,63.79 101.12,63.65 100.94,63.65 100.76,63.83 100.76,64.01 100.9,64.15 100.9,64.33 94.79,70.43 77.16,70.43 R273.1
N101507457: length 30.9
  TOP w0.127: R274.1 79.14,70.13 94.59,70.13 97.6,67.12 97.6,66.94 97.46,66.8 97.46,66.62 97.6,66.49 97.78,66.49 97.91,66.62 98.09,66.62 98.27,66.45 98.27,66.27 98.14,66.13 98.14,65.95 98.32,65.77 98.5,65.77 98.63,65.91 98.81,65.91 98.99,65.73 98.99,65.55 98.85,65.41 98.85,65.23 99.03,65.05 99.21,65.05 99.35,65.19 99.53,65.19 99.71,65.01 99.71,64.83 99.57,64.69 99.57,64.51 99.75,64.33 99.93,64.33 100.07,64.47 100.25,64.47 100.43,64.29 100.43,63.53 100.8,63.16 101.3,63.16 101.42,63.03 101.42,62.78 101.3,62.65 101.18,62.65 101.05,62.52 U14.5
N101507470: length 29.5
  TOP w0.127: U14.7 99.45,62.42 99.33,62.55 99.19,62.55 99.06,62.67 99.06,62.93 99.19,63.05 99.96,63.05 100.09,63.18 100.09,63.49 99.85,63.72 99.67,63.72 99.47,63.52 99.29,63.52 99.11,63.7 99.11,63.88 99.31,64.08 99.31,64.26 99.13,64.44 98.95,64.44 98.82,64.31 98.64,64.31 98.48,64.46 98.48,64.69 98.59,64.8 98.59,64.98 96.92,66.65 96.92,66.83 97.06,66.97 97.06,67.15 96.88,67.33 96.7,67.33 96.56,67.19 96.38,67.19 96.2,67.37 96.2,67.55 96.34,67.69 96.34,67.87 96.16,68.05 95.98,68.05 95.84,67.91 95.66,67.91 95.48,68.09 95.48,68.27 95.62,68.41 95.62,68.59 95.44,68.77 95.26,68.77 95.13,68.63 94.95,68.63 94.77,68.81 94.77,68.99 94.9,69.13 94.9,69.31 94.39,69.82 81.12,69.82 R275.1
N101507472: length 27
  TOP w0.127: R276.1 83.05,69.22 92.2,69.22 92.32,69.09 92.32,68.83 92.45,68.71 92.71,68.71 92.83,68.83 92.83,69.09 92.96,69.22 93.34,69.22 93.54,69.02 93.54,68.84 93.02,68.33 93.02,68.15 93.2,67.97 93.38,67.97 93.9,68.48 94.08,68.48 94.25,68.31 94.25,68.13 93.74,67.61 93.74,67.43 93.92,67.25 94.1,67.25 94.61,67.77 94.79,67.77 94.96,67.6 94.96,67.42 94.69,67.16 94.69,66.98 94.84,66.83 95.02,66.83 95.26,67.07 95.49,67.07 97.74,64.82 97.74,64.03 97.87,63.9 98.04,63.9 98.17,63.77 98.17,63.52 98.04,63.39 97.87,63.39 97.74,63.26 97.74,62.72 97.87,62.6 98.53,62.6 98.65,62.47 U14.8
N101507474: length 26.1
  TOP w0.127: R277.1 84.7,68.83 91.82,68.83 94.34,66.32 94.52,66.32 94.6,66.4 94.78,66.4 94.96,66.22 94.96,66.04 94.12,65.19 94.12,65.02 94.27,64.86 94.45,64.86 95.69,66.11 95.87,66.11 96.03,65.95 96.03,65.77 95.54,65.29 95.54,65.11 95.72,64.93 95.9,64.93 96.41,65.44 96.59,65.44 96.77,65.26 96.77,65.08 96.26,64.57 96.26,64.39 96.43,64.22 96.61,64.22 96.92,64.54 97.26,64.54 97.41,64.39 97.41,63.98 97.28,63.85 96.62,63.85 96.49,63.72 96.49,63.45 96.62,63.33 97.28,63.33 97.41,63.2 97.41,62.56 97.28,62.44 97.18,62.44 97.05,62.31 U14.10
N101507491: length 25.1
  TOP w0.127: R278.1 86.66,68.5 91.64,68.5 91.91,68.24 91.91,68.06 91.39,67.54 91.39,67.36 91.57,67.18 91.75,67.18 92.27,67.7 92.45,67.7 92.63,67.52 92.63,67.34 92.05,66.77 92.05,66.59 92.23,66.41 92.41,66.41 92.99,66.98 93.17,66.98 93.34,66.8 93.34,66.62 92.77,66.05 92.77,65.87 92.95,65.69 93.13,65.69 93.7,66.26 93.88,66.26 94.06,66.08 94.06,65.9 93.48,65.32 93.48,65.14 94.38,64.24 94.56,64.24 95.14,64.83 95.32,64.83 95.47,64.68 95.47,64.5 95.01,64.04 95.01,63.86 95.19,63.68 95.37,63.68 95.82,64.14 96.01,64.14 96.18,63.97 96.18,63.79 95.78,63.4 95.78,63.13 95.91,63 96.76,63 96.9,62.87 96.9,62.61 96.77,62.48 96.38,62.48 96.25,62.36 U14.11
N101507493: length 23.9
  TOP w0.127: U14.13 94.65,62.4 94.97,62.71 94.97,62.89 94.7,63.16 94.52,63.16 93.88,62.51 93.7,62.51 93.52,62.69 93.52,62.87 93.97,63.33 93.97,63.51 93.31,64.17 93.13,64.17 92.36,63.4 92.18,63.4 92,63.58 92,63.76 92.83,64.59 92.83,64.77 92.65,64.95 92.48,64.95 91.63,64.11 91.45,64.11 91.27,64.29 91.27,64.47 92.12,65.31 92.12,65.49 91.94,65.67 91.76,65.67 90.79,64.71 90.61,64.71 90.43,64.89 90.43,65.07 91.36,66 91.36,66.18 91.18,66.36 91,66.36 90.2,65.55 90.02,65.55 89.84,65.73 89.84,65.91 90.68,66.75 90.68,68.07 90.55,68.2 88.51,68.2 R279.1
N101507495: length 22.2
  TOP w0.127: U14.42 94.65,47.42 94.4,47.17 93.73,47.17 93.6,47.04 93.6,46.79 93.73,46.66 94.53,46.66 94.65,46.53 94.65,44.87 94.49,44.7 94.23,44.7 94.11,44.83 94.11,45.21 93.98,45.34 93.73,45.34 93.6,45.21 93.6,44.07 93.47,43.94 93.28,43.94 93.16,44.07 93.16,44.2 93.03,44.32 92.78,44.32 92.65,44.2 92.65,43.94 92.52,43.81 92.27,43.81 92.14,43.94 92.14,44.2 92.01,44.32 91.76,44.32 91.63,44.2 91.63,43.94 91.51,43.81 91.25,43.81 91.13,43.94 91.13,44.2 91,44.32 90.74,44.32 90.62,44.2 90.62,44.07 90.49,43.94 90.24,43.94 90.11,44.07 90.11,44.2 89.98,44.32 89.73,44.32 89.6,44.2 89.6,43.94 89.47,43.81 89.22,43.81 89.09,43.94 89.09,44.2 88.97,44.32 88.71,44.32 88.59,44.2 88.59,44.07 88.46,43.94 88.2,43.94 88.08,44.07 88.08,44.2 87.95,44.32 87.7,44.32 87.57,44.2 87.57,43.94 87.44,43.81 87.19,43.81 87.06,43.94 87.06,44.2 86.93,44.32 86.68,44.32 86.55,44.2 86.55,44.07 86.43,43.94 86.1,43.94 R283.1
N101507512: length 17.1
  TOP w0.127: R284.1 87.62,42.93 93.85,42.93 96.25,45.33 96.25,45.55 96.13,45.68 95.63,45.68 95.5,45.8 95.5,46.06 95.63,46.18 96.13,46.18 96.25,46.31 96.25,46.57 96.13,46.69 95.63,46.69 95.5,46.82 95.5,47.07 95.63,47.2 96.48,47.2 96.65,47.37 96.65,47.84 96.52,47.96 96.38,47.96 96.25,48.09 U14.44
N101507514: length 25.3
  TOP w0.127: R285.1 81.41,42.16 81.41,41.78 81.53,41.66 81.79,41.66 81.92,41.78 81.92,42.01 82.04,42.14 87.73,42.14 88.14,42.55 94.11,42.55 96.65,45.09 96.65,45.72 96.8,45.87 97.41,45.87 97.54,46 97.54,46.25 97.41,46.38 96.8,46.38 96.67,46.51 96.67,46.76 96.8,46.89 97.92,46.89 98.04,47.01 98.04,47.27 97.92,47.39 97.18,47.39 97.05,47.52 U14.45
N101507516: length 20.5
  TOP w0.127: R286.1 83.61,41.83 88.06,41.83 88.42,42.19 94.26,42.19 98.42,46.35 98.42,48.01 98.65,48.23 U14.47
N101507533: length 22
  TOP w0.127: U14.48 99.45,45.99 99.06,45.59 98.88,45.59 98.8,45.66 98.62,45.66 98.44,45.48 98.44,45.3 98.52,45.23 98.52,45.05 98.34,44.87 98.16,44.87 98.08,44.94 97.9,44.94 97.72,44.77 97.72,44.59 97.8,44.51 97.8,44.33 97.62,44.15 97.44,44.15 97.36,44.23 97.18,44.23 97.01,44.05 97.01,43.87 97.08,43.79 97.08,43.61 96.9,43.43 96.72,43.43 96.65,43.51 96.47,43.51 96.29,43.33 96.29,43.15 96.36,43.07 96.36,42.89 96.18,42.71 96,42.71 95.93,42.79 95.75,42.79 95.57,42.61 95.57,42.43 95.64,42.35 95.64,42.17 95.46,42 95.28,42 95.21,42.07 95.03,42.07 94.85,41.89 94.85,41.71 94.92,41.64 94.92,41.46 94.69,41.22 85.67,41.22 R287.1
N101507535: length 20.5
  TOP w0.127: U14.50 101.05,48.09 100.86,47.9 100.86,47.24 100.73,47.12 100.48,47.12 100.35,47.24 100.35,47.6 100.23,47.73 99.95,47.73 99.82,47.6 99.82,45.92 94.79,40.89 87.37,40.89 R280.1
N101507537: length 18.5
  TOP w0.127: R281.1 89.27,40.51 91.31,40.51 91.44,40.39 91.69,40.39 91.82,40.51 92.08,40.51 92.34,40.25 92.57,40.25 92.83,40.5 93.08,40.5 93.33,40.25 93.59,40.25 93.84,40.5 94.1,40.5 94.35,40.25 94.6,40.25 101.85,47.5 U14.51
N101507548: length 17
  TOP w0.127: U14.53 103.45,48.56 94.77,39.88 R282.1
N101509422: length 32.9
  TOP w0.127: v1(72.26,59.18) R297.2 ; v1(86.94,62.74) 87.45,62.23 U14.22
  BOTTOM w0.127: v1(72.26,59.18) 71.63,59.82 71.63,62.98 71.86,63.21 72.04,63.21 72.43,62.83 72.61,62.83 72.79,63.01 72.79,63.19 72.4,63.57 72.4,63.75 72.58,63.93 72.76,63.93 73.15,63.55 73.33,63.55 73.51,63.73 73.51,63.91 73.12,64.29 73.12,64.47 74.18,65.53 74.18,65.79 74.31,65.91 74.56,65.91 74.69,65.79 74.69,65.53 74.81,65.41 75.07,65.41 75.2,65.53 75.2,65.79 75.32,65.91 75.58,65.91 75.7,65.79 75.7,65.53 75.83,65.41 76.08,65.41 76.21,65.53 76.21,65.79 76.34,65.91 76.59,65.91 76.72,65.79 76.72,65.53 76.85,65.41 77.1,65.41 77.23,65.53 77.23,65.79 77.35,65.91 77.61,65.91 77.74,65.79 77.74,65.53 77.86,65.41 78.12,65.41 78.24,65.53 78.24,65.79 78.37,65.91 78.62,65.91 78.75,65.79 78.75,65.53 78.88,65.41 79.13,65.41 79.26,65.53 79.26,65.79 79.39,65.91 79.64,65.91 79.77,65.79 79.77,65.53 79.89,65.41 80.15,65.41 80.28,65.53 80.28,65.79 80.4,65.91 80.66,65.91 80.78,65.79 80.78,65.53 80.91,65.41 81.16,65.41 81.29,65.53 81.29,65.79 81.42,65.91 81.67,65.91 81.8,65.79 81.8,65.53 81.93,65.41 85.22,65.41 86.94,63.68 v1(86.94,62.74)
N101509590: length 30.5
  TOP w0.127: R291.2 73.15,61.09 75.56,63.5 76.32,63.5 76.44,63.37 76.44,62.23 76.57,62.1 76.82,62.1 76.95,62.23 76.95,63.37 77.08,63.5 77.33,63.5 77.46,63.37 77.46,62.23 77.59,62.1 77.84,62.1 77.97,62.23 77.97,63.37 78.09,63.5 78.35,63.5 78.47,63.37 78.47,62.23 78.6,62.1 78.86,62.1 78.98,62.23 78.98,63.37 79.11,63.5 79.36,63.5 79.49,63.37 79.49,62.23 79.62,62.1 79.87,62.1 80,62.23 80,63.37 80.13,63.5 81.92,63.5 82.25,63.83 87.68,63.83 89.05,62.46 U14.20
N101509597: length 31.4
  TOP w0.127: R293.2 71.62,60.25 72.08,60.71 72.64,60.71 72.77,60.58 74.13,60.58 74.39,60.83 74.39,61.34 74.51,61.47 74.77,61.47 74.9,61.34 74.9,60.83 75.02,60.71 75.28,60.71 75.4,60.83 75.4,61.59 75.53,61.72 75.78,61.72 75.91,61.59 75.91,60.83 76.04,60.71 76.29,60.71 76.42,60.83 76.42,61.59 76.55,61.72 76.8,61.72 76.93,61.59 76.93,60.83 77.05,60.71 77.31,60.71 77.44,60.83 77.44,61.59 77.56,61.72 77.82,61.72 77.94,61.59 77.94,60.83 78.07,60.71 78.32,60.71 78.45,60.83 78.45,61.59 78.58,61.72 78.83,61.72 78.96,61.59 78.96,60.83 79.09,60.71 79.34,60.71 79.47,60.83 79.47,61.59 79.59,61.72 79.85,61.72 79.98,61.59 79.98,60.83 80.1,60.71 80.26,60.71 80.39,60.83 80.39,63.07 80.52,63.2 82.12,63.2 82.45,63.53 87.55,63.53 88.25,62.83 U14.21
N101509855: length 36.2
  TOP w0.127: U14.37 90.65,47.98 v1(90.55,47.88) 90.04,47.37 90.04,46.91 89.92,46.79 86.94,46.79 86.74,46.99 81.73,46.99 81.58,47.14 81.58,47.88 81.45,48.01 81.22,48.01 81.09,47.88 81.09,47.12 80.97,46.99 80.71,46.99 80.58,47.12 80.58,48.64 80.45,48.77 80.2,48.77 80.07,48.64 80.07,47.12 79.94,46.99 79.69,46.99 79.56,47.12 79.56,48.64 79.43,48.77 79.18,48.77 79.05,48.64 79.05,47.12 78.93,46.99 78.67,46.99 78.54,47.12 78.54,48.64 78.42,48.77 78.16,48.77 78.04,48.64 78.04,47.62 77.91,47.5 77.66,47.5 77.53,47.62 77.53,48.39 77.4,48.51 75.74,48.51 75.61,48.64 75.61,49.15 75.48,49.28 75.23,49.28 75.1,49.15 75.1,48.9 74.98,48.77 R306.2
  BOTTOM w0.127: v1(90.55,47.88) 91.82,47.88 92.33,48.39 93.6,48.39 94.36,49.15 R178.1
N101509857: length 15.9
  TOP w0.127: R309.2 85.21,44.57 85.34,44.69 85.66,44.69 85.79,44.57 85.79,44.45 85.92,44.32 86.17,44.32 86.3,44.45 86.3,44.57 86.43,44.69 92.97,44.69 93.1,44.82 93.1,45.58 93.23,45.71 94.12,45.71 94.24,45.84 94.24,46.09 94.12,46.22 93.23,46.22 93.1,46.35 93.1,47.36 92.25,48.21 U14.39
N101509859: length 22.2
  TOP w0.127: R310.2 90.16,66.92 89.52,66.28 83.38,66.28 83.24,66.14 83.24,65.91 83.37,65.79 89.03,65.79 90.42,64.39 90.68,64.39 92,63.07 92.51,63.07 93.1,63.67 93.28,63.67 93.46,63.49 93.46,63.31 93.05,62.9 U14.15
N101509861: length 30
  TOP w0.127: U14.18 90.65,62.38 90.17,62.87 89.56,62.87 87.99,64.44 81.86,64.44 81.36,64.95 76.16,64.95 76.03,65.07 76.03,65.41 75.9,65.53 75.65,65.53 75.52,65.41 75.52,65.07 75.4,64.95 75.14,64.95 75.02,65.07 75.02,65.41 74.89,65.53 74.17,65.53 74.02,65.38 74.02,65.2 74.16,65.07 74.16,64.89 73.98,64.71 73.8,64.71 73.66,64.84 73.48,64.84 73.3,64.66 73.3,64.48 73.44,64.35 73.44,64.17 73.26,63.99 73.08,63.99 72.94,64.13 72.76,64.13 72.58,63.95 72.58,63.77 72.72,63.63 72.72,63.45 72.54,63.27 72.36,63.27 72.22,63.41 72.04,63.41 71.86,63.23 71.86,63.05 72,62.91 72,62.73 71.82,62.55 71.64,62.55 71.5,62.69 71.32,62.69 71.12,62.48 70.42,62.48 70.29,62.36 70.29,62.23 70.16,62.1 69.91,62.1 69.78,62.23 69.78,62.36 69.65,62.48 69.34,62.48 69.21,62.36 R308.2
N101509863: length 31.2
  TOP w0.127: U14.16 92.25,62.23 92.04,62.44 91.66,62.44 90.47,63.63 89.71,63.63 88.27,65.07 82.17,65.07 82.04,65.2 82.04,66.17 81.92,66.29 81.62,66.29 81.49,66.17 81.49,65.79 81.36,65.66 81.11,65.66 80.98,65.79 80.98,66.17 80.85,66.29 74,66.29 70.83,63.12 67.18,63.12 R304.2
N101510168: length 33.2
  TOP w0.127: R307.2 67.89,62.81 70.95,62.81 74.05,65.91 76.32,65.91 76.45,65.79 76.45,65.41 76.57,65.28 76.83,65.28 76.95,65.41 76.95,65.79 77.08,65.91 77.34,65.91 77.46,65.79 77.46,65.38 77.59,65.25 77.84,65.25 77.97,65.38 77.97,65.79 78.1,65.91 78.35,65.91 78.48,65.79 78.48,65.38 78.61,65.25 78.86,65.25 78.99,65.38 78.99,65.79 79.11,65.91 79.37,65.91 79.49,65.79 79.49,65.38 79.62,65.25 79.88,65.25 80,65.38 80,65.79 80.13,65.91 80.38,65.91 80.51,65.79 80.51,65.41 80.64,65.28 81.51,65.28 82.04,64.74 88.16,64.74 89.66,63.25 90.42,63.25 91.45,62.22 U14.17
N101511316: length 36.1
  TOP w0.127: R311.2 69.6,60.83 69.85,61.09 69.85,61.59 69.98,61.72 70.48,61.72 70.61,61.85 70.61,61.98 70.73,62.1 70.99,62.1 71.12,61.98 71.12,61.85 71.24,61.72 71.5,61.72 71.58,61.8 71.76,61.8 72.09,61.47 72.27,61.47 72.45,61.65 72.45,61.83 72.12,62.16 72.12,62.34 72.3,62.52 72.48,62.52 72.81,62.19 72.99,62.19 73.16,62.37 73.16,62.55 72.84,62.88 72.84,63.06 73.02,63.24 73.2,63.24 73.52,62.91 73.7,62.91 73.88,63.09 73.88,63.27 73.56,63.6 73.56,63.78 73.74,63.96 73.92,63.96 74.24,63.63 74.42,63.63 74.6,63.81 74.6,63.99 74.27,64.32 74.27,64.5 74.42,64.64 74.73,64.64 74.85,64.52 74.85,64.39 74.98,64.26 75.24,64.26 75.36,64.39 75.36,64.52 75.49,64.64 75.74,64.64 75.87,64.52 75.87,64.39 76,64.26 76.25,64.26 76.38,64.39 76.38,64.52 76.51,64.64 76.76,64.64 76.89,64.52 76.89,64.39 77.01,64.26 77.27,64.26 77.39,64.39 77.39,64.52 77.52,64.64 77.78,64.64 77.9,64.52 77.9,64.39 78.03,64.26 78.28,64.26 78.41,64.39 78.41,64.52 78.54,64.64 78.79,64.64 78.92,64.52 78.92,64.39 79.05,64.26 79.3,64.26 79.43,64.39 79.43,64.52 79.55,64.64 79.81,64.64 79.93,64.52 79.93,64.39 80.06,64.26 80.32,64.26 80.44,64.39 80.44,64.52 80.57,64.64 81.15,64.64 81.66,64.14 87.83,64.14 89.48,62.48 89.73,62.48 89.85,62.36 U14.19 89.85,59.63 v1(90.81,58.67)
  BOTTOM w0.127: R176.2 v1(90.81,58.67)
N101583028: length 1.8
  BOTTOM w0.127: SW8.5 96.9,56.26
N101594808: length 2.1
  TOP w0.127: U1.54 46.36,48.89 TP25.1

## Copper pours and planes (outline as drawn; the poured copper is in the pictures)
5V_SDA_PSW on TOP: 133.1,72.52 133.1,71.12 133.22,70.99 135,70.99 135.13,71.12 135.13,71.75 134.37,72.52 134.37,73.4 134.3,73.47 134.18,73.47 134.11,73.39 134.11,73.18 133.98,73.06 133.64,73.06
5V_SYS on TOP: 18.8,46.99 18.67,46.86 18.67,46.35 18.54,46.23 16,46.23 15.75,46.48 15.75,51.05 15.24,51.56 15.24,65.02 16.32,66.1 17.21,66.1 17.27,66.17 20.32,66.17 20.45,66.04 20.45,64.9 20.32,64.77 18.92,64.77 18.16,64.01 18.16,52.32 18.92,51.56 21.59,51.56 21.72,51.44 21.72,47.37 21.34,46.99
5V_SYS on TOP: 15.88,21.84 11.05,26.67 11.05,40.01 12.95,41.91 16,41.91 16.26,41.66 16.26,40.64 14.61,38.99 14.61,30.54 19.11,26.04 27.43,26.04 27.56,25.91 27.56,24 27.94,23.62 27.94,21.97 27.81,21.84
5V_SYS on BOTTOM: 15.3,44.51 15.3,47.43 15.49,47.62 18.41,47.62 18.67,47.37 18.67,42.8 15.75,39.88 13.59,39.88 13.08,40.39 13.08,42.29
5V_USB_OTG on TOP: 8.51,51.18 8.89,50.8 8.89,50.42 9.02,50.29 9.27,50.29 9.33,50.23 9.33,50.09 9.28,50.04 8.26,50.04 7.75,49.53 7.75,48.64 8.51,47.88 8.51,47.24 8.38,47.12 7.49,47.12 7.24,47.37 6.1,47.37 5.97,47.5 5.97,50.93 6.22,51.18
GND on TOP (solid shape): 42.04,65.61 42.04,65.53 35.75,65.53 35.75,66.15 34.89,67.02 34.89,68.54 35.04,68.69 38.95,68.69
GND on TOP (solid shape): 36.7,37.68 36.77,37.77 36.88,37.75 37.58,37.05 37.58,35.4 36.7,35.4
GND on TOP (solid shape): 81.73,32.06 81.75,31.95 81.65,31.89 81.14,31.89 80.03,33 80.03,33.15 80.64,33.15
GND on TOP (solid shape): 75.74,37.27 75.77,37.16 75.67,37.1 75.04,37.1 72.88,39.26 72.12,39.26 72.12,39.5 72.16,39.5 72.16,40.01 72.12,40.01 72.12,40.2 72.81,40.2
GND on TOP (solid shape): 118.5,62.23 118.16,61.9 118.14,61.9 117.96,61.87 117.8,61.77 117.77,61.73 117.41,62.09 117.41,62.16 117.4,62.23 117.93,62.76 118.5,62.76
GND on TOP (solid shape): 78.75,23.16 78.78,23.2 78.84,23.19 78.88,23.15 79.36,23.15 79.36,22.88 79.65,22.59 79.88,22.59 79.88,21.95 79.63,21.95 79.63,21.99 79.12,21.99 79.12,21.95 78.87,21.95 78.87,21.74 78.75,21.74
GND on TOP (solid shape): 72.33,14.42 72.44,14.44 72.5,14.35 72.5,8.89 70.84,8.89 67.6,12.13 67.58,12.24 67.67,12.31 70.21,12.31
GND on TOP (solid shape): 92.05,50.9 92.08,50.85 92.07,50.8 92.03,50.77 89.32,50.77 89.28,50.8 89.28,50.85 89.3,50.9 89.7,51.29 91.66,51.29
GND on TOP (solid shape): 101.99,15.66 102.09,15.68 102.16,15.61 103.64,15.61 103.76,15.49 103.76,14.87 102.16,14.87 102.09,14.8 101.99,14.82 101.57,15.24
GND on TOP (solid shape): 11.17,49.16 11.17,48.39 10.95,48.39 10.89,48.3 10.79,48.31 10.74,48.35 10.68,48.38 10.68,49.46 10.33,49.81 10.32,49.87 10.37,49.9 10.43,49.9
GND on TOP (solid shape): 102.56,32.95 102.58,32.84 102.49,32.78 96.5,32.78 96.19,33.09 96.19,33.12 96.19,33.19 96.18,33.26 96.19,33.35 96.27,33.39 102.12,33.39
GND on TOP (solid shape): 83.42,25.6 83.49,25.57 83.52,25.51 83.53,25.43 83.55,25.35 83.55,25.05 83.52,25.02 83.49,24.99 82.55,24.99 82.55,24.24 82.3,24.24 82.3,24.28 81.8,24.28 81.8,25.18 81.92,25.3 83.28,25.3 83.28,25.54 83.32,25.54 83.39,25.61
GND on TOP (solid shape): 30.56,28.55 30.67,28.57 30.73,28.48 30.73,27.2 31.08,26.86 31.1,26.75 31.01,26.68 26.31,26.68 25.91,26.29 24.38,26.29 24.38,27.3 24.51,27.3 24.51,28.32 24.38,28.32 24.38,28.45 30.46,28.45
GND on TOP (solid shape): 117.71,75.9 117.81,75.87 119.12,74.56 119.13,74.56 119.18,74.52 119.17,74.47 119.12,74.42 117.11,74.42 117.11,75.28 117.37,75.54 117.38,75.55 117.54,75.66 117.64,75.83
GND on TOP (solid shape): 13.51,50.76 13.51,49.59 13.78,49.59 13.88,49.52 13.86,49.41 13.41,48.97 12.86,48.97 12.86,48.01 12.8,47.92 12.69,47.94 12.67,47.96 12.67,48.39 12.54,48.39 12.54,49.43 12.7,49.43 12.7,50.96 13.31,50.96
GND on TOP (solid shape): 76.18,62.12 76.37,61.92 76.17,61.72 75.9,61.99 75.42,61.99 75.13,61.7 75.06,61.63 74.96,61.65 74.88,61.74 74.4,61.74 74.12,61.45 74.12,60.94 74.02,60.85 73.53,60.85 73.44,60.91 73.46,61.02 75.68,63.23 76.18,63.23
GND on TOP (solid shape): 21.31,35.8 23.49,35.8 23.49,35.56 21.99,35.56 21.99,35.31 21.95,35.31 21.95,34.8 21.99,34.8 21.99,34.54 22.14,34.54 22.14,33.67 21.29,33.67 21.29,32.39 20.7,32.39 20.7,33.51 20.45,33.51 20.45,33.55 19.94,33.55 19.94,33.51 19.68,33.51 19.68,33.29 19.56,33.29 19.56,33.62 19.31,33.62 19.31,34.02 19.87,34.02 19.87,34.7 19.96,34.7 20.47,35.21 21.08,35.21 21.08,36.18 21.31,36.18
GND on TOP (solid shape): 23.27,34.54 23.31,34.51 23.3,34.46 23.24,34.4 23.24,33.67 23.24,33.67 23.24,31.94 23.24,31.94 23.24,31.77 23.52,31.5 25.65,31.5 25.65,30.97 25.53,30.84 25.53,30.2 25.29,29.97 24.53,29.97 24.08,29.52 23.55,29.52 23.53,29.53 23.53,31.05 22.91,31.05 22.91,31.19 22.72,31.37 22.6,31.37 22.48,31.49 22.48,31.94 22.88,31.94 22.88,33.67 22.68,33.67 22.68,34.54
GND on TOP (solid shape): 45.62,46.62 45.72,46.56 45.69,46.45 45.36,46.12 44.83,46.12 44.83,46.08 44.58,46.08 44.58,45.62 43.08,45.62 42.78,45.32 42.67,45.3 42.61,45.39 42.61,46.04 42.9,46.34 43.05,46.34 43.05,46.12 43.31,46.12 43.31,46.08 43.82,46.08 43.82,46.12 44.07,46.12 44.07,46.62
GND on TOP (solid shape): 30.75,73.02 30.75,71.64 30.34,71.23 30.34,63.6 30.1,63.6 30.1,61.88 30.34,61.88 30.34,60.58 30.28,60.49 30.17,60.51 29.86,60.82 29.86,63.91 30.1,63.91 30.1,65.63 29.86,65.63 29.86,71.14 30.37,71.64 30.37,71.79 30.61,71.79 30.61,72.75 30.35,72.75 30.35,72.79 29.84,72.79 29.84,72.75 29.59,72.75 29.59,72.54 29.31,72.54 28.46,73.39 28.72,73.65 30.12,73.65
GND on TOP (solid shape): 117.84,64.99 117.84,64.86 118.28,64.43 118.36,64.36 118.46,64.32 118.5,64.31 118.5,63.48 117.85,63.48 117.85,63.42 117.73,63.42 117.36,63.06 117.25,63.04 117.19,63.13 117.19,63.3 117.62,63.72 117.62,64.34 117.62,64.35 117.65,64.52 117.62,64.68 117.62,64.69 117.62,64.99 117.64,65.01 117.82,65.01
GND on TOP (solid shape): 12.02,53.7 12.16,53.67 12.3,53.68 12.39,53.67 12.43,53.59 12.43,52.59 12.7,52.32 12.7,51.92 12.45,51.92 12.45,51.96 11.94,51.96 11.94,51.92 11.68,51.92 11.68,50.83 10.67,50.83 10.58,50.89 10.6,51.01 10.92,51.33 10.92,53.59 11.65,53.59 11.65,53.71 12.01,53.71
GND on TOP (solid shape): 28.84,72.01 28.9,72.1 29.02,72.08 29.09,72 29.59,72 29.59,71.79 29.63,71.79 29.68,71.75 29.67,71.7 29.32,71.36 29.32,65.63 29.08,65.63 29.08,63.91 29.32,63.91 29.32,60.96 29.26,60.87 29.15,60.89 28.84,61.2 28.84,61.88 29.08,61.88 29.08,63.6 28.84,63.6
GND on TOP (solid shape): 95.06,50.89 95.06,50.77 94.12,50.77 94.12,48.13 94.39,48.13 94.39,47.53 94.29,47.44 93.62,47.44 93.54,47.36 93.43,47.34 93.37,47.43 93.37,47.47 92.88,47.96 92.86,48.07 92.95,48.13 93.59,48.13 93.59,50.77 92.88,50.77 92.84,50.8 92.84,50.85 92.86,50.9 93.25,51.29 94.65,51.29
GND on TOP (solid shape): 78.92,30.66 78.92,30.19 78.86,30.09 78.75,30.11 78.63,30.24 78.29,30.24 77.83,29.77 77.81,29.77 77.74,29.84 77.74,29.86 78.2,30.32 78.2,30.66 77.91,30.95 77.57,30.95 77.49,30.87 77.47,30.87 77.4,30.94 77.4,30.96 77.48,31.04 77.48,31.38 77.19,31.67 76.85,31.67 76.77,31.59 76.75,31.59 76.69,31.66 76.69,31.68 76.76,31.76 76.76,32.1 75.57,33.29 75.55,33.4 75.65,33.46 76.11,33.46
GND on TOP (solid shape): 38.37,37.08 38.43,37.18 38.54,37.15 39.74,35.96 39.74,34.38 39.7,34.34 39.66,34.3 39.57,34.26 39.49,34.31 39.37,34.46 39.22,34.56 39.17,34.64 39.09,34.67 38.89,34.67 38.82,34.65 38.77,34.59 38.76,34.56 38.48,34.56 38.48,35.4 38.37,35.4
